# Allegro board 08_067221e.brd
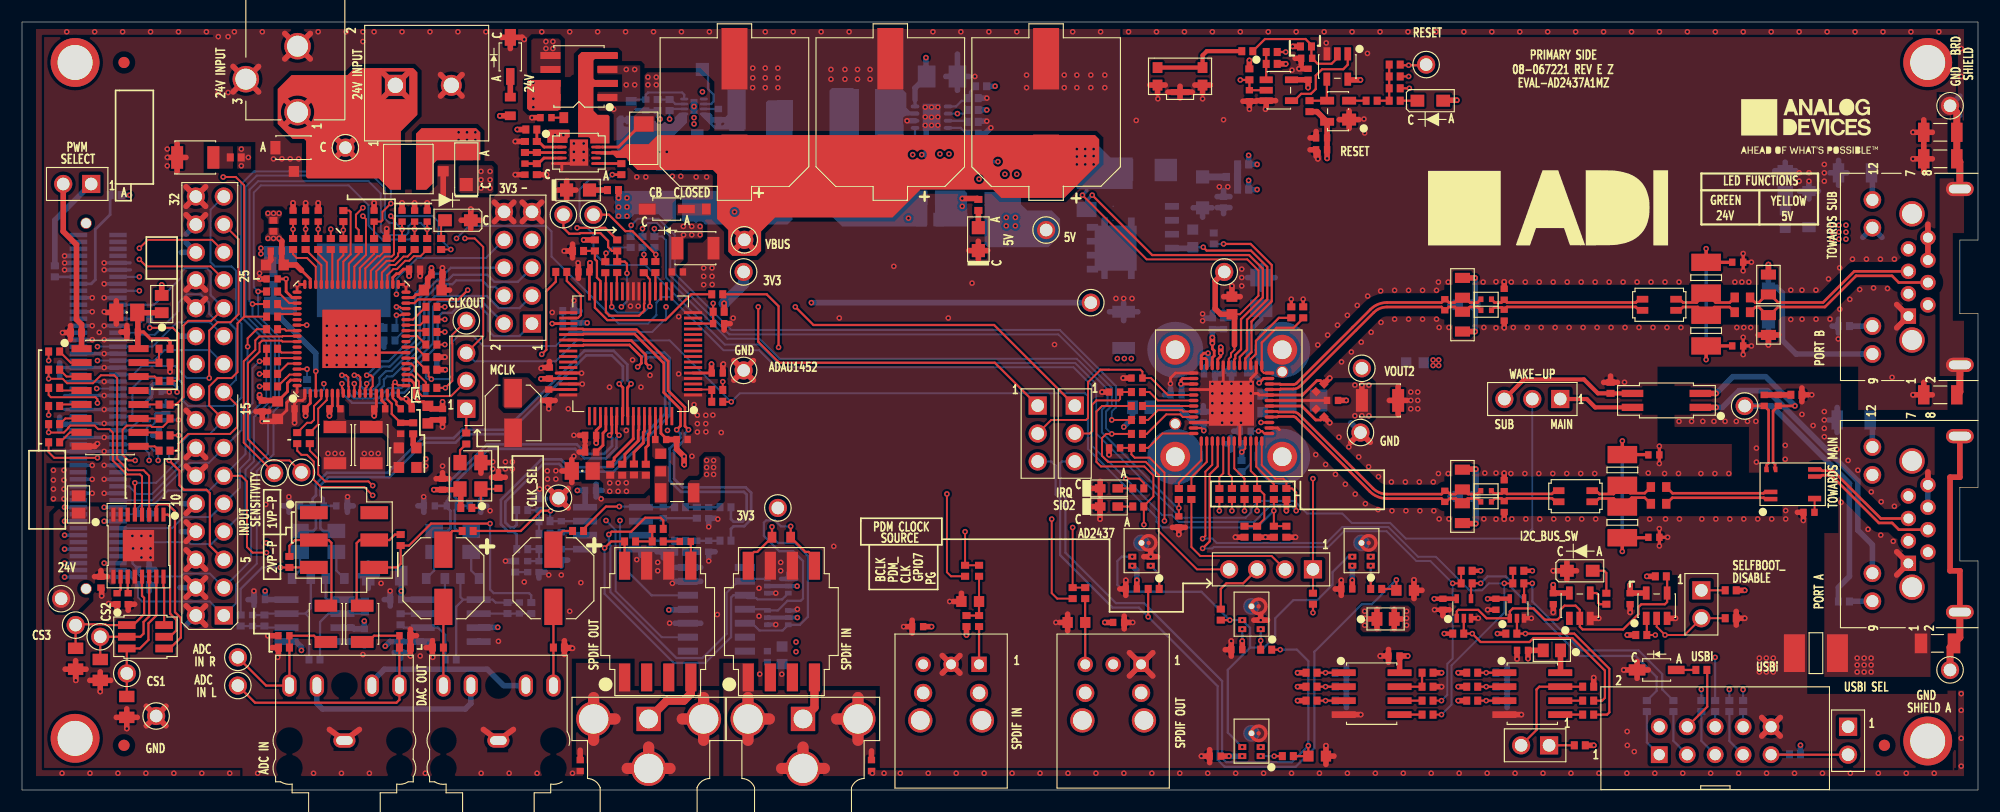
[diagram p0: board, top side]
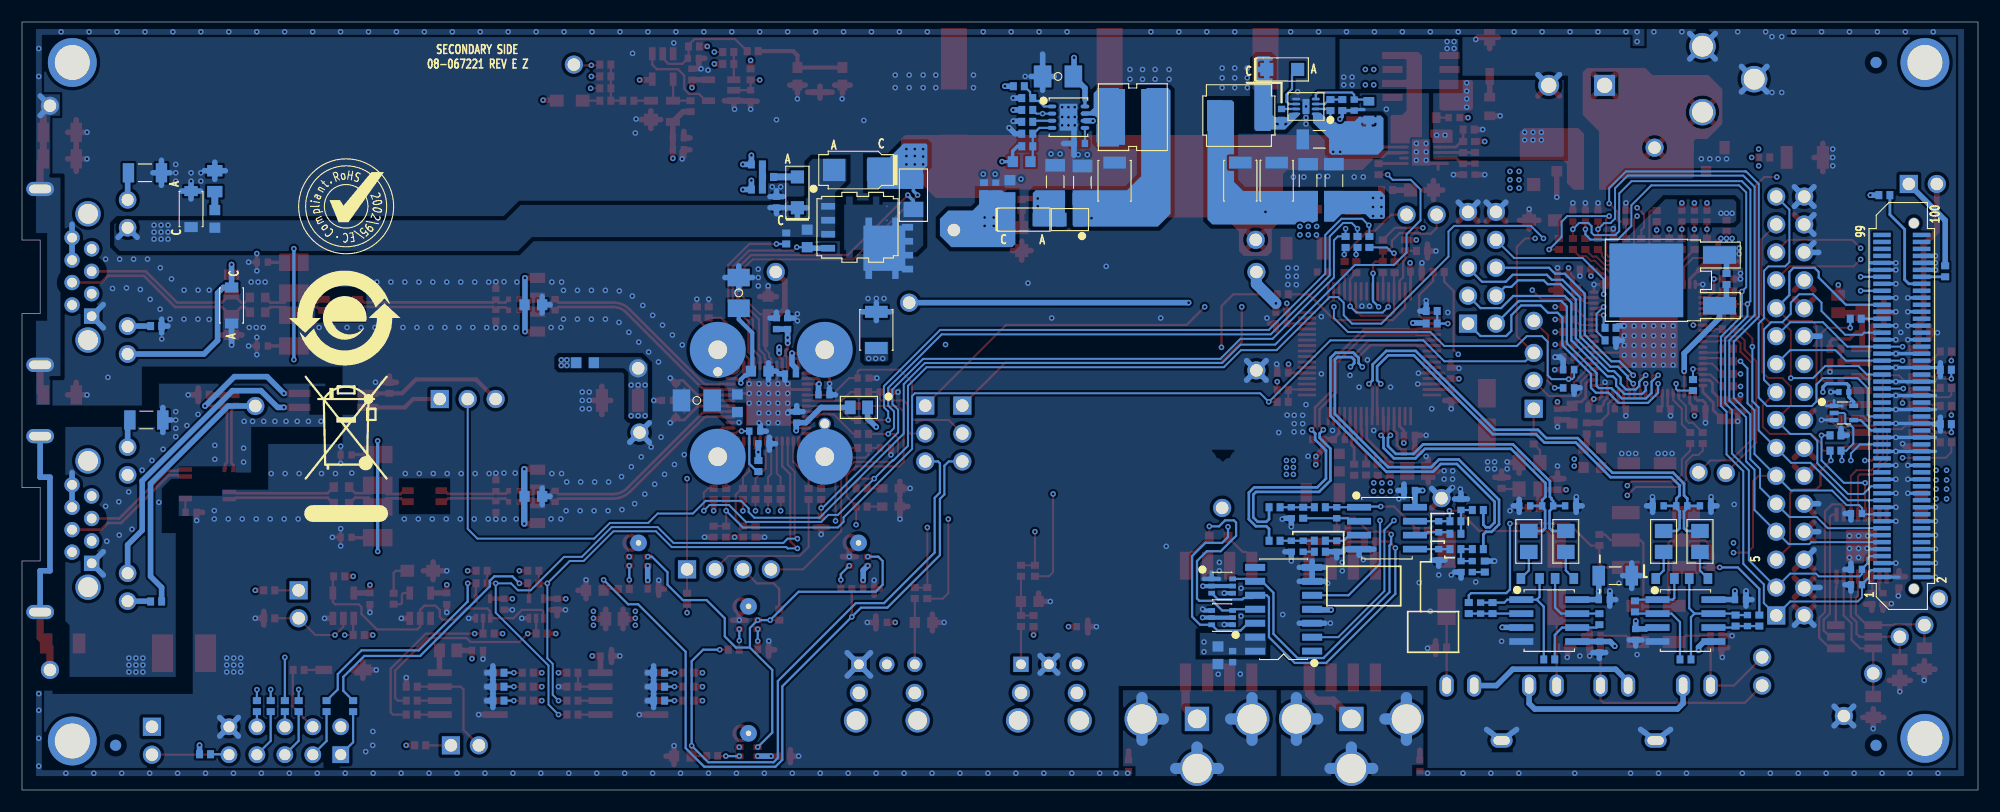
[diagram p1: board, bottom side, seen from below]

Outline 177.8 x 69.85 mm; copper layers: TOP, L2_GND, L3_SIG, L4_PWR, L5_GND, BOTTOM. Coordinates in mm from the lower left corner of the outline.
Outline path: 0,69.85 0,0 177.8,0 177.8,20.84 176.15,20.84 176.15,27.54 177.8,27.54 177.8,43.31 176.15,43.31 176.15,50.01 177.8,50.01 177.8,69.85 0,69.85

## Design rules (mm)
constraint set DEFAULT: min track width 0.178
net group AD243X_A: nets AD243X_AN AD243X_AP
net group AD243X_B: nets AD243X_BN AD243X_BP
net group ADC1L: nets ADC1LN ADC1LP
net group ADC1R: nets ADC1RN ADC1RP
net group DAC1L: nets DAC1LN DAC1LP
net group DAC1R: nets DAC1RN DAC1RP
net group DP1: nets UNNAMED_4_CAP_I21_N2 UNNAMED_4_CAP_I25_N2
net group DP2: nets UNNAMED_4_CAP_I73_N1 UNNAMED_4_CAP_I74_N2
net group DP3: nets UNNAMED_5_CAP_I145_N2 UNNAMED_5_CAP_I146_N2
net group DP4: nets UNNAMED_4_CAP_I139_N1 UNNAMED_4_TRANOPTO4PV2_I78_C
net group DP5: nets UNNAMED_4_CAP_I21_N1 UNNAMED_4_CAP_I25_N1
net group DP6: nets UNNAMED_5_CAP_I100_N2 UNNAMED_5_CAP_I105_N1
net group DP7: nets UNNAMED_5_CAP_I146_N1 UNNAMED_5_FLTR4PV7_I16_N3
net group DP_A2B: nets UNNAMED_4_MODRJE7318800XXX_I171_4 UNNAMED_4_MODRJE7318800XXX_I171_5

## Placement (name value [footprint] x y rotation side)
C1  0.1uF  [C0402]  116.9 65.09 270 top
C2  0.1uF  [C0402]  111.57 63.14 90 top
C3  0.1uF  [C0402]  47.62 61.15 0 top
C4  0.1uF  [C0402]  136.4 12.7 180 top
C5  0.1uF  [C0402]  118.13 59.31 0 top
C6  4.7NF  [C0402]  45.72 56.47 90 top
C7  0.1uF  [C0603]  25.52 56.26 0 top
C8  0.1uF  [C0603]  38.29 57.07 90 top
C9  27pF  [C0402]  36.83 52.2 270 top
C10  27pF  [C0402]  35.69 52.2 270 top
C11  27pF  [C0402]  34.54 52.2 270 top
C12  27pF  [C0402]  32 52.2 270 top
C13  0.1uF  [C0603]  110.74 38.1 0 bottom
C14  4.7uF  [C1206H71]  112.65 45.21 270 bottom
C15  0.1uF  [C0402]  8.64 17.4 90 top
C16  27pF  [C0402]  26.92 52.2 270 top
C17  27pF  [C0402]  25.78 52.2 270 top
C18  27pF  [C0402]  24.64 52.2 270 top
C19  47uF  [CPLSMSQ260H240]  48.3 19.26 90 top
C20  10UF  [C1210-2]  63.75 55.42 270 bottom
C21  10UF  [C1210-2]  67.06 55.42 270 bottom
C22  0.1uF  [C0402]  110.36 31.5 0 bottom
C23  0.1uF  [C0402]  23.11 49.02 180 top
C24  0.033uF  [C0402]  155.96 48.01 180 top
C25  4.7NF  [C0402]  81.68 58.8 180 bottom
C26  0.1uF  [C0402]  35.69 47.37 180 top
C27  0.1uF  [C0402]  22.73 46.48 0 top
C28  10UF  [C1210-2]  78.49 55.41 270 bottom
C29  4.7uF  [C0603]  88.01 54.67 270 bottom
C30  12pF  [C0402]  129.33 26.71 270 top
C31  0.1uF  [C0603]  112.78 35.17 270 bottom
C32  4.7uF  [C1206H71]  116.46 35.43 180 bottom
C33  0.33uF  [C0603]  131.32 26.71 0 bottom
C34  27pF  [C0402]  134.73 25.78 90 top
C35  27pF  [C0402]  134.73 27.68 90 top
C36  0.1uF  [C0402]  37.72 46.86 180 top
C37  1uF  [C0805H60]  9.52 43.43 0 top
C38  0.1uF  [C0402]  10.03 41.66 0 top
C39  0.033uF  [C0402]  155.96 40.39 0 top
C40  0.1uF  [C0402]  107.38 33.91 270 bottom
C41  27pF  [C0402]  101.35 37.46 180 top
C42  0.1uF  [C0402]  38.23 34.16 90 top
C43  0.1uF  [C0402]  117.98 34.29 135 top
C44  4700pF  [C0402]  159.64 35.43 90 top
C45  12pF  [C0402]  129.33 44.13 270 top
C46  0.1uF  [C0603]  109.98 44.07 270 top
C47  10uF  [CAPSML169W169H217]  44.64 34.29 270 top
C48  0.33uF  [C0603]  131.32 44.13 0 bottom
C49  27pF  [C0402]  134.73 43.19 90 top
C50  27pF  [C0402]  134.73 45.09 90 top
C51  27pF  [C0402]  99.31 36.2 180 top
C52  0.1uF  [C0402]  21.84 34.92 90 top
C53  0.01uF  [C0603#2]  156.38 43.46 0 top
C54  0.01uF  [C0603#2]  156.38 44.79 0 top
C55  0.1uF  [C0402]  117.98 36.58 225 top
C56  0.1uF  [C0402]  25.27 34.67 0 top
C57  10NF  [C0402]  119.13 35.43 180 top
C58  150pF  [C0402]  34.42 32.89 270 top
C59  10UF  [C1210-2]  123.44 35.43 180 top
C60  390pF  [C0402]  58.05 31.88 180 top
C61  0.1uF  [C0402]  32.51 34.67 0 top
C62  0.1uF  [C0402]  28.45 34.67 0 top
C63  5600pF  [C0603]  58.05 29.78 90 top
C64  27pF  [C0402]  99.31 31.12 180 top
C65  0.033uF  [C0402]  148.34 22.99 180 top
C66  0.1uF  [C0402]  51.07 47.12 0 top
C67  0.1uF  [C0402]  38.23 27.81 90 top
C68  0.01uF  [C0603#2]  148.76 26.03 0 top
C69  0.01uF  [C0603]  22.99 47.75 0 top
C70  0.01uF  [C0603#2]  148.76 27.55 0 top
C71  27pF  [C0402]  105.16 24.38 90 top
C72  0.033uF  [C0402]  162.43 25.26 180 top
C73  0.01uF  [C0603]  37.34 45.47 180 top
C74  10UF  [C1210-2]  15.75 57.53 0 top
C75  0.1uF  [C0402]  120.42 18.29 0 top
C76  0.01uF  [C0603]  23.24 34.54 90 top
C77  0.1uF  [C0402]  100.84 18.29 0 top
C78  0.01uF  [C0603]  36.89 34.14 90 top
C79  10UF  [C1210-2]  31.75 31.37 90 top
C80  0.033uF  [C0402]  148.34 30.48 0 top
C81  10UF  [C1210-2]  28.45 31.37 90 top
C82  22uF  [C1206]  32.97 19.49 0 bottom
C83  47uF  [C0805H60]  50.93 29.02 0 top
C84  33pF  [C0603]  125.73 18.16 180 top
C85  0.1uF  [C0402]  7.18 18.9 90 top
C86  5600pF  [C0603]  35.05 31.12 0 top
C87  0.1uF  [C0402]  9.65 17.4 90 top
C88  0.1uF  [C0402]  37.21 38.23 180 bottom
C89  0.1uF  [C0402]  110.42 12.76 0 top
C90  10UF  [C1210-2]  30.92 15.11 90 top
C91  10UF  [C1210-2]  27.62 15.11 90 top
C92  100pF  [C0402]  34.81 14.03 180 top
C93  100pF  [C0402]  23.81 14.03 0 top
C94  0.1uF  [C0402]  124.71 12.19 180 top
C95  0.1uF  [C0402]  59.58 47.12 180 top
C96  0.1uF  [C0402]  108.46 3.08 0 top
C97  0.1uF  [C0402]  109.22 42.42 270 bottom
C98  4700pF  [C0402]  158.37 35.43 90 top
C99  0.01uF  [C1206]  174.12 13.33 0 top
C100  33pF  [C0603]  117.73 3.08 180 top
C101  4.7uF  [C1206H71]  83.63 64.9 180 bottom
C102  0.01uF  [C1812H110]  163.07 12.45 0 top
C103  330uF  [CPLSMSQ512H650]  78.93 61.66 90 top
C104  330uF  [CPLSMSQ512H650]  93.09 61.66 90 top
C105  0.1uF  [C0402]  56.71 62.29 90 bottom
C106  270pF  [C0402]  62.42 25.22 90 bottom
C107  0.1uF  [C0402]  47.94 37.93 270 top
C108  0.1uF  [C0402]  60.01 31.88 180 top
C109  0.1uF  [C0402]  51.69 32.26 0 top
C110  0.1uF  [C0402]  63.2 37.93 180 top
C111  10UF  [C1210-2]  61.21 49.28 180 top
C112  0.1uF  [C0402]  51.69 30.73 0 top
C113  0.1uF  [C0402]  63.31 61.44 270 bottom
C114  1uF  [C1206]  59.88 59.18 180 bottom
C115  10pF  [C0603]  86.93 57.15 180 bottom
C116  0.033uF  [C0402]  109.22 53.47 90 bottom
C117  0.1uF  [C0603]  160.27 51.94 90 bottom
C118  22uF  [C1206]  60.9 55.42 270 bottom
C119  22uF  [C1206]  58.55 55.42 270 bottom
C120  22uF  [C1206]  83.88 55.31 270 bottom
C121  22uF  [C1206]  81.41 55.26 270 bottom
C122  0.033uF  [C0402]  89.28 54.74 270 bottom
C123  10UF  [C1210-2]  100.14 41.85 270 bottom
C124  10NF  [C0402]  108.2 42.42 270 bottom
C125  27pF  [C0402]  37.21 36.58 0 bottom
C126  10NF  [C0402]  107.95 37.85 180 bottom
C127  0.1uF  [C0402]  47.88 35.93 90 top
C128  0.1uF  [C0402]  104.9 35.94 0 bottom
C129  0.1uF  [C0402]  34.92 34.67 0 top
C130  47uF  [CPLSMSQ260H240]  38.3 19.26 90 top
C131  0.1uF  [C0402]  116.78 66.55 0 top
C132  330uF  [CPLSMSQ512H650]  64.76 61.66 90 top
C133  1000pF  [C0402]  41.2 25.84 180 bottom
C134  100pF  [C0402]  39.12 25.84 0 bottom
C135  1000pF  [C0402]  37.03 25.84 0 bottom
C136  1000pF  [C0402]  29.08 25.84 180 bottom
C137  0.1uF  [C0402]  31.12 14.15 90 bottom
C138  0.1uF  [C0402]  34.42 13.01 90 bottom
C139  100pF  [C0402]  26.92 25.84 180 bottom
C140  1000pF  [C0402]  24.77 25.84 0 bottom
C141  27pF  [C0402]  11.05 25.15 0 bottom
C142  10uF  [C0805H53]  40.83 22.61 90 bottom
C143  10uF  [C0805H53]  37.47 22.61 90 bottom
C144  10uF  [C0805H53]  28.57 22.61 90 bottom
C145  0.1uF  [C0402]  33.97 17.32 0 bottom
C146  0.1uF  [C0402]  21.59 17.32 0 bottom
C147  10uF  [C0805H53]  25.27 22.61 90 bottom
C148  560pF  [C0402]  62.42 22.17 270 bottom
C149  270pF  [C0402]  47 25.97 270 bottom
C150  560pF  [C0402]  46.99 20.32 270 bottom
C151  27pF  [C0402]  11.05 18.67 0 bottom
C152  27pF  [C0402]  11.05 20.07 0 bottom
C153  47PF  [C0402]  77.22 2.22 90 top
C154  0.1uF  [C0402]  51.68 27.24 180 bottom
C155  68PF  [C0402]  58.29 25.22 90 bottom
C156  4.7uF  [C0603]  69.09 12.26 90 bottom
C157  270pF  [C0402]  20.96 15.41 90 bottom
C158  270pF  [C0402]  45.21 16.55 90 bottom
C159  0.1uF  [C0402]  67.75 12.13 90 bottom
C160  0.1uF  [C0402]  60.29 22.61 180 top
C161  150PF  [C0402]  58.29 22.17 90 bottom
C162  0.1uF  [C0402]  63.33 42.42 180 top
C163  0.1uF  [C0402]  118.13 58.23 0 top
C164  68PF  [C0402]  49.02 23.95 90 bottom
C165  150PF  [C0402]  49.02 21.41 90 bottom
C166  10uF  [C0402]  61.34 22.17 90 bottom
C167  10uF  [C0402]  45.97 20.32 90 bottom
C168  47PF  [C0402]  50.74 2.22 90 top
C169  0.1uF  [C0402]  146.18 17.4 270 top
C170  0.1uF  [C0402]  133.98 16.89 270 top
C171  0.1uF  [C0402]  129.16 16.89 270 top
C172  0.1uF  [C0402]  139.19 17.4 90 top
C173  0.1uF  [C0402]  111.19 32.64 0 bottom
C174  0.01uF  [C0603]  106.43 50.16 270 bottom
C175  0.1uF  [C0402]  12.19 36.2 180 bottom
C176  0.1uF  [C0402]  81.41 14.86 0 top
C177  33pF  [C0603]  86.19 17.14 0 top
C178  33pF  [C0603]  95.85 15.24 0 top
C179  0.1uF  [C0402]  99.69 15.24 180 top
D1  PMEG6010CEH,115  [SOD123F]  63.25 65.53 180 bottom
D2  PMEG6010CEH,115  [SOD123F]  86.74 51.88 180 bottom
D3  TPSMF4L30A  [SOD123FL]  24.68 58.42 180 top
D4  TPSMF4L30A  [SOD123FL]  162.43 52.83 90 bottom
D5  NRVTSA3100ET3G  [SMA]  101.98 56.39 0 bottom
D6  PMEG6010CEH,115  [SOD123F]  107.31 54.36 90 bottom
D7  PMEG6010CEH,115  [SOD123F]  40.39 56.47 90 top
D8  BAT54XY,115  [SOT363H43]  68.71 15.68 90 bottom
D9  BAT54XY,115  [SOT363H43]  68.71 18.55 270 bottom
D10  TPSMF4L30A  [SOD123FL]  158.75 44.07 270 bottom
DS1  HSMS-C170  [LED0805]  128.02 62.69 0 top
DS2  CMD28-21VGC/TR8  [LEDCMD28-21B]  44.39 66.67 270 top
DS3  CMD28-21VGC/TR8  [LEDCMD28-21B]  58.61 52.83 0 top
DS4  HSMA-C170-T0000  [LED0805]  39.62 51.82 180 top
DS5  CMD28-21VGC/TR8  [LEDCMD28-21B]  148.59 10.92 0 top
DS6  CLX6F-FKC-CNP1ST1E1BB7D3D3  [LEDSMSQ134H114]  11.22 13.94 270 top
DS7  SML-LXT0805GW-TR  [LXT0805]  86.93 50.1 90 top
DS8  SML-LXT0805GW-TR  [LXT0805]  50.55 54.57 0 top
DS9  APT1608LVBC/D  [LED0603]  98.81 27.43 0 top
DS10  APT1608LVBC/D  [LED0603]  98.81 25.78 0 top
DS11  HSMS-C170  [LED0805]  141.6 19.94 0 top
E1  600OHM AT 100MEGHZ  [L0603-2]  101.73 34.8 0 bottom
E2  600 OHM AT 100 MEGHZ  [L0603]  126.62 38.86 180 bottom
E3  600OHM AT 100MEGHZ  [L0603-2]  82.55 51.88 0 bottom
E6  600OHM AT 100MEGHZ  [L0603]  35.05 29.34 180 top
E9  600OHM AT 100MEGHZ  [L0603-2]  12.7 44.2 90 top
E11  600OHM AT 100MEGHZ  [L0603-2]  5.14 25.97 90 top
E12  600OHM AT 100MEGHZ  [L0603-2]  123.95 15.56 0 top
E16  600OHM AT 100MEGHZ  [L0603-2]  139.06 12.7 180 top
E18  470OHM AT 100MEGHZ  [L0603]  59.75 52.26 180 bottom
FL1  ACT1210L-101-2P-TL00  [FLSML154W98H98]  148.83 44.13 0 top
FL2  ACT1210L-101-2P-TL00  [FLSML154W98H98]  141.21 26.72 0 top
JP1  TSW-104-07-G-S  [CNTHMHDR1X4L400W98H343]  117.35 20.07 180 top
JP2  TSW-102-07-G-S  [CNTHMHDR1X2L200W98H343]  152.65 18.16 270 top
JP3  TSW-102-07-G-S  [CNTHMHDR1X2L200W98H343]  138.81 4.06 180 top
JP4  TSW-103-07-G-S  [CNTHMHDR1X3L300W98H343]  139.83 35.56 180 top
JP6  TSW-103-07-G-S  [CNTHMHDR1X3L300W98H343]  92.32 34.96 270 top
JP9  TSW-103-07-G-S  [CNTHMHDR1X3L300W98H343]  95.69 34.96 270 top
JP38  TSW-103-07-G-S  [CNTHMHDR1X3L300W98H343]  40.39 34.67 90 top
JP42  HTSW-102-07-T-S  [CNTHMHDR1X2L200W98H343]  165.99 5.75 270 top
JP47  TSW-102-07-G-S  [CNTHMHDR1X2L200W98H343]  6.29 55.12 180 top
L1  3.3UH  [L0805H57]  158.75 45.97 90 top
L2  3.3UH  [L0805H57]  130.93 25.18 90 top
L3  3.3UH  [L0805H57]  130.93 28.23 90 top
L4  180NH  [L0402-3]  133.08 26.21 0 top
L5  180NH  [L0402-3]  133.08 27.21 0 top
L6  3.3UH  [L0805H57]  158.75 42.29 90 top
L7  4.7UH  [LSML213W201H59]  67.18 61.34 0 bottom
L8  3.3UH  [L0805H57]  130.94 42.6 90 top
L9  3.3UH  [L0805H57]  130.94 45.67 90 top
L10  180NH  [L0402-3]  133.09 43.63 0 top
L11  180NH  [L0402-3]  133.09 44.63 0 top
L12  100uH  [LSMSQ189H118_A]  76.83 61.19 180 bottom
L13  4.7uH  [LSMSQ157H122]  35.12 56.48 0 top
NOREF  -  []  0 0 90 top
NOREF#2  -  []  177.8 27.54 0 top
NOREF#3  -  []  177.8 0 0 top
NOREF#4  -  []  162.18 60.32 0 top
NOREF#5  -  []  176.15 20.84 0 top
NOREF#6  -  [unnamed#2]  4.83 4.7 0 top
NOREF#7  -  []  82.3 159.61 0 top
NOREF#8  -  []  0 69.85 0 top
NOREF#9  -  []  230.93 275.67 0 top
NOREF#10  -  []  0 69.85 0 top
NOREF#11  -  []  -22.8 311.15 0 top
NOREF#12  -  []  -39.78 -55.14 0 top
NOREF#13  -  []  42.06 169.52 0 top
NOREF#14  -  []  80.58 133.99 0 top
NOREF#15  -  []  -39.78 -55.14 0 top
NOREF#16  -  []  0 69.85 0 top
NOREF#17  -  []  28.65 159.61 90 top
NOREF#18  -  []  42.06 159.61 0 top
NOREF#19  -  [unnamed#2]  9.27 4.06 0 top
NOREF#20  -  []  79.63 80.67 0 top
NOREF#21  -  []  160.8 33.66 0 top
NOREF#22  -  []  0 0 0 top
NOREF#23  -  []  177.8 50.01 0 top
NOREF#24  -  []  177.8 69.85 180 top
NOREF#25  -  []  176.35 47.65 0 top
NOREF#26  -  []  216.22 239.52 0 top
NOREF#27  -  []  4.83 4.7 0 top
NOREF#28  -  []  177.8 0 90 top
NOREF#29  -  []  157.86 11.43 0 top
NOREF#30  -  []  177.8 0 90 top
NOREF#31  -  []  -39.78 -55.14 0 top
NOREF#32  -  []  177.8 20.84 0 top
NOREF#33  -  []  194.8 11.19 0 top
NOREF#34  -  []  -39.78 -55.14 0 top
NOREF#35  -  []  28.49 -59.81 270 top
NOREF#36  -  []  4.83 4.7 0 top
NOREF#37  -  []  111.76 4.45 0 top
NOREF#38  -  []  127.81 49.53 0 top
NOREF#39  -  []  177.8 43.31 0 top
NOREF#40  -  [unnamed#2]  9.27 66.17 0 top
NOREF#41  -  []  0 0 0 top
NOREF#42  -  []  0 69.85 270 top
NOREF#43  -  [unnamed#2]  173.23 66.17 0 top
NOREF#44  -  [unnamed#2]  4.83 66.17 0 top
NOREF#45  -  [unnamed#2]  173.23 4.46 0 top
NOREF#46  -  [unnamed#2]  169.29 4.06 0 top
NOREF#47  -  []  0 0 0 top
NOREF#48  -  []  62.28 169.52 0 top
NOREF#49  -  []  116.1 28.77 0 top
NOREF#50  -  []  62.18 159.61 0 top
NOREF#51  -  [unnamed#2]  169.29 4.06 180 bottom
NOREF#52  -  []  148.46 42.93 180 bottom
NOREF#53  -  [unnamed#2]  9.27 4.06 180 bottom
NOREF#54  -  []  148.34 53.09 180 bottom
NOREF#55  -  [unnamed#2]  9.27 66.17 180 bottom
NOREF#56  -  []  139.06 41.27 180 bottom
P1  PJ-102AH  [CNCUI-PJ-102A_SLOTPAD]  25.05 61.65 90 top
P2  1716020000  [CNWEIDMULLER171602]  33.94 64.09 0 top
P3  RCJ-011  [CNCUIRCJ-01]  70.99 6.46 180 top
P4  FCR684208R  [CNCLIFF_FCR684208R]  86.99 11.43 180 top
P5  RCJ-011  [CNCUIRCJ-01]  56.96 6.46 180 top
P6  FCR684208T  [CNCLIFF_FCR684208T]  101.73 11.43 180 top
P8  TSW-105-07-G-D  [CNSAMTEC2X5H338LD36]  46.36 42.42 90 top
P10  RJE73-188-00210  [MRJE73-188-00XXX]  171.47 43.09 90 top
P15  TSW-116-08-G-D  [CNBERG2X16H330LD36]  18.34 15.88 90 top
P22  RJE73-188-00210  [MRJE73-188-00XXX]  171.47 20.62 90 top
P23  TESTPAD  [TPC65D45]  127.63 65.98 90 top
P28  SJ1-3525NG  [CNCUISJ1-3525NG]  43.3 4.5 90 top
P29  SJ1-3525NG  [CNCUISJ1-3525NG]  29.31 4.5 90 top
P30  N2510-6002-RB  [CN3MN2510-6002RB]  148.83 3.21 0 top
P32  LSS-150-01-L-DV-A-K  [CNSAMTECLSS-150-01-X-DV-A]  6.93 34.92 90 bottom
Q1  DMNH6022SSDQ-13  [SO8NB-5]  50.63 64.9 90 top
Q2  TLX9291A(GBTPL,F  [SO4H96]  149.48 35.43 90 top
Q3  STD2805T4  [TO252]  27.56 46.35 90 bottom
Q4  DMTH8012LPSQ-13  [POWERDI5060-8]  101.85 51.18 270 bottom
R1  100  [R0402]  113.6 67.12 180 top
R2  10K  [R0402]  113.6 66.04 180 top
R3  0  [R0402]  124.78 65.98 180 top
R4  1K  [R0402]  124.78 62.69 0 top
R5  10K  [R0402]  111.57 65.09 270 top
R6  0  [R0402]  124.78 64.9 180 top
R7  10K  [R0402]  110.86 29.46 90 bottom
R8  0  [R0402]  122.68 62.69 180 top
R9  10K  [R0402]  117.03 62.19 90 top
R10  4.7K  [R0603]  44.39 62.17 270 top
R11  33  [R0402]  109.98 26.92 90 top
R12  10K  [R0402]  113.79 23.49 270 top
R13  22K  [R0603]  50.1 61.15 0 top
R14  33  [R0402]  106.3 26.92 90 top
R15  10K  [R0402]  131.83 10.67 180 top
R16  10K  [R0402]  134.49 10.67 180 bottom
R17  4.42MEG  [R0402]  46.3 60.07 180 top
R18  0.012  [R1206-2]  56.52 59.27 270 top
R19  10K  [R0402]  131.83 9.4 180 top
R20  88.7K  [R0402]  46.8 58.48 90 top
R21  10K  [R0402]  114.93 23.49 90 top
R22  10K  [R0402]  112.27 23.49 270 top
R23  11.3K  [R0402]  45.72 58.48 270 top
R24  10K  [R0402]  134.49 9.4 180 bottom
R25  33  [R0402]  142.37 8.13 0 top
R26  10K  [R0402]  131.83 8.13 180 top
R27  1MEG  [R0402]  54.48 56.47 270 top
R28  0  [R0402]  46.8 56.47 270 top
R29  33  [R0402]  142.37 6.86 0 top
R30  10K  [R0402]  134.49 8.13 180 bottom
R31  0  [R1206]  174.37 59.82 0 top
R32  4.7K  [R0603]  63.06 52.83 0 top
R33  1K  [R0402]  53.72 54.57 0 top
R34  475  [R0402]  101.47 25.78 0 top
R35  33  [R0402]  127.76 8.13 0 top
R36  1K  [R0402]  86.93 53.21 90 top
R37  0  [R0402]  22.86 51.31 90 top
R38  475  [R0402]  101.47 27.43 0 top
R39  2.55K  [R0402]  135.38 14.22 180 top
R40  100  [R1210]  145.47 24.34 90 top
R41  100  [R1210]  145.47 29.11 270 top
R42  10K  [R0402]  144.4 36.58 270 top
R43  0  [R0402]  54.56 29.13 270 top
R44  33  [R0402]  36.83 49.66 90 top
R45  33  [R0402]  35.69 49.66 90 top
R46  205  [R0402]  165.61 17.14 180 bottom
R47  33  [R0402]  34.54 49.66 90 top
R48  33  [R0402]  32 49.66 90 top
R49  33  [R0402]  29.21 52.2 270 top
R50  33  [R0402]  26.92 49.66 90 top
R51  33  [R0402]  25.78 49.66 90 top
R52  33  [R0402]  24.64 49.66 90 top
R53  2.55K  [R0402]  130.56 14.22 180 top
R54  0  [R0402]  101.35 36.2 0 top
R55  0  [R0402]  136.02 18.8 180 top
R56  120  [R1210]  153.09 46.59 270 top
R57  0  [R0402]  54.1 49.53 90 top
R58  33  [R0402]  56.52 47.55 270 top
R59  33  [R0402]  53.02 47.55 270 top
R60  0  [R0402]  53.47 29.13 270 top
R61  0  [R0402]  56.71 29.13 270 top
R62  0  [R0402]  22.73 45.34 180 top
R63  0  [R0402]  22.73 44.2 180 top
R64  33  [R0402]  37.21 43.94 180 top
R65  100  [R0402]  161.29 35.94 180 top
R66  33  [R0402]  22.73 43.05 0 top
R67  33  [R0402]  22.73 41.91 0 top
R68  33  [R0402]  22.73 38.99 0 top
R69  33  [R0402]  30.61 49.66 270 top
R70  0  [R0402]  131.32 18.8 180 top
R71  33  [R0402]  22.73 36.7 0 top
R72  100K  [R0402]  116.46 43.44 270 top
R73  100K  [R0402]  115.38 43.44 270 top
R74  10K  [R0402]  141.6 4.06 0 top
R75  3.32K  [R0402]  38.1 49.66 90 top
R76  33  [R0402]  37.21 42.8 0 top
R77  0  [R0402]  37.21 41.66 0 top
R78  120  [R1210]  153.09 41.78 90 top
R79  0  [R0402]  37.21 40.51 0 top
R80  10K  [R0402]  4.91 41.6 180 top
R81  33  [R0402]  22.73 40.13 0 top
R82  10K  [R0402]  12.95 38.86 0 top
R83  10K  [R0402]  12.95 40.13 0 top
R84  33  [R0402]  28.07 49.66 90 top
R85  0  [R0402]  37.21 39.37 0 top
R86  0  [R0402]  2.92 39.88 0 top
R87  0  [R0402]  22.73 37.85 0 top
R88  33  [R0402]  37.21 36.58 0 top
R89  0  [R0402]  12.95 37.21 180 top
R90  33  [R0402]  2.92 38.23 180 top
R91  0  [R0402]  63.2 35.31 0 top
R92  0  [R0402]  2.92 36.58 0 top
R93  100K  [R0402]  155.32 15.62 180 top
R94  0  [R0402]  63.2 36.39 0 top
R95  10K  [R0402]  147.19 14.1 180 top
R96  0  [R1206]  174.37 35.94 0 top
R97  0  [R0402]  2.92 34.92 0 top
R98  33  [R0402]  101.35 34.92 0 top
R99  4.32K  [R0402]  35.56 32.89 270 top
R100  0  [R0402]  12.95 35.05 180 top
R101  10K  [R0402]  116.71 67.63 0 top
R102  33  [R0402]  2.92 33.27 180 top
R103  33  [R0402]  86.99 15.37 90 top
R104  33  [R0402]  57.57 47.56 270 top
R105  33  [R0402]  54.1 47.56 90 top
R106  0  [R0402]  12.95 33.78 180 top
R107  10K  [R0402]  37.21 38.23 180 top
R108  33  [R0402]  12.95 32.26 0 top
R109  33  [R0402]  40.39 31.97 90 top
R110  10K  [R0402]  43.31 27.94 270 top
R111  0  [R0402]  2.92 31.62 0 top
R112  0  [R1206]  174.37 57.4 0 top
R113  0  [R0402]  12.95 30.86 180 top
R114  33  [R0402]  101.35 31.12 0 top
R115  10K  [R0402]  40.39 25.65 180 top
R116  33  [R0402]  26.16 32 270 top
R117  562  [R1206]  59.55 27.03 180 top
R118  10K  [R0402]  114.93 26.92 90 top
R119  10K  [R0402]  85.85 15.37 90 top
R120  33  [R0402]  108.84 26.92 90 top
R121  33  [R0402]  105.16 26.92 90 top
R122  2.55K  [R0402]  131.32 19.94 0 top
R123  5.36K  [R0402]  34.42 22.73 270 top
R124  0  [R0402]  55.63 29.15 270 top
R125  0  [R0402]  117.35 17.4 90 top
R126  2.55K  [R0402]  136.02 19.94 0 top
R127  0  [R0402]  86.99 19.94 90 top
R128  100K  [R0402]  48.8 12.95 180 top
R129  5.36K  [R0402]  24.31 20.74 270 top
R130  33  [R0402]  123.1 18.29 0 top
R131  33  [R0402]  102.87 18.29 180 top
R132  33  [R0402]  49.02 47.12 180 top
R133  10K  [R0402]  119.89 8.13 180 bottom
R134  0  [R0402]  124.78 63.82 180 top
R135  10K  [R0402]  111.12 23.49 90 top
R136  100  [R0402]  111.38 67.19 0 top
R137  10K  [R0402]  117.22 8.13 180 top
R138  33  [R0402]  63.2 45.09 0 top
R139  10K  [R0402]  117.22 9.4 180 top
R140  33  [R0402]  29.21 49.66 90 top
R141  33  [R0402]  113.1 12.76 0 top
R142  10K  [R0402]  52.07 49.53 90 top
R143  10K  [R0402]  50.55 49.02 0 top
R144  100K  [R0402]  34.81 12.95 180 top
R145  100K  [R0402]  23.81 12.95 0 top
R146  10K  [R0402]  119.89 9.4 180 bottom
R147  10K  [R0402]  119.89 10.67 180 bottom
R148  10K  [R0402]  117.22 10.67 180 top
R149  100K  [R0402]  2.92 33.27 180 bottom
R150  100K  [R0402]  2.92 38.23 180 bottom
R151  10  [R0805]  4.87 11.94 90 top
R152  10  [R0805]  7.11 10.92 90 top
R153  10  [R0805]  9.52 7.56 90 top
R154  10K  [R0402]  87.19 64.01 180 bottom
R155  1K  [R0402]  152.65 10.92 0 top
R156  100K  [R0402]  12.95 32.26 0 bottom
R157  0  [R0402]  108.97 15.95 90 top
R158  33  [R0402]  115.06 3.08 0 top
R159  100K  [R0402]  86.42 62.93 180 bottom
R160  31.6K  [R0402]  58.86 62.29 90 bottom
R161  100K  [R0402]  86.42 61.85 0 bottom
R162  24.9K  [R0603]  55.37 61.79 270 bottom
R163  0  [R0402]  86.42 60.77 180 bottom
R164  10.2K  [R0402]  86.42 59.69 180 bottom
R165  0  [R0402]  111 54.61 0 bottom
R166  0  [R0402]  111 56.9 0 bottom
R167  53.6K  [R0402]  86.42 58.55 0 bottom
R168  12  [R0805]  160.27 55.37 90 bottom
R169  0  [R0402]  8.51 54.1 0 bottom
R170  100K  [R0402]  90.36 54.74 270 bottom
R171  0  [R0402]  57.48 49.85 90 bottom
R172  0  [R0402]  56.4 49.85 90 bottom
R173  0  [R0402]  55.33 49.85 90 bottom
R174  0  [R0402]  2.98 47.17 90 bottom
R175  1K  [R0402]  22.86 46.48 90 bottom
R176  1K  [R0402]  33.15 49.66 90 top
R177  0  [R0402]  11.11 42.86 180 bottom
R178  10K  [R0402]  33.4 40.89 0 bottom
R179  10K  [R0402]  33.4 42.04 0 bottom
R180  10K  [R0402]  155.32 18.16 0 top
R181  0  [R0402]  108.33 50.16 90 bottom
R182  0.05  [R1206-2]  96.77 54.1 90 bottom
R183  33  [R0402]  25.91 36.83 90 bottom
R184  10K  [R0402]  57.79 62.29 90 bottom
R185  10K  [R0402]  49.66 42.43 0 bottom
R186  0.5  [R0402]  19.43 57.53 0 top
R187  10K  [R0402]  63.33 43.5 180 top
R188  75  [R0603]  69.02 22.99 180 top
R189  0  [R0402]  12.95 30.86 0 bottom
R190  10K  [R0402]  49.66 43.56 180 bottom
R192  5.62K  [R0402]  63.94 22.67 180 bottom
R193  33  [R0402]  25.02 32 90 top
R194  11K  [R0402]  63.94 25.72 180 bottom
R195  33  [R0402]  112.27 26.92 90 top
R196  237  [R0603]  40.7 19.24 0 bottom
R197  237  [R0603]  37.59 19.24 180 bottom
R198  237  [R0603]  28.45 19.24 0 bottom
R199  33  [R0402]  111.12 26.92 90 top
R200  237  [R0603]  25.4 19.24 180 bottom
R201  5.36K  [R0402]  31.18 16.7 90 bottom
R202  5.36K  [R0402]  34.42 15.54 90 bottom
R203  33  [R0402]  127.76 6.86 0 top
R204  5.36K  [R0402]  22.03 15.41 90 bottom
R205  5.36K  [R0402]  19.88 15.41 270 bottom
R206  249  [R0402]  57.79 23.75 180 top
R207  5.36K  [R0402]  46.29 16.55 270 bottom
R208  5.36K  [R0402]  44.13 16.55 90 bottom
R209  110  [R0402]  55.28 22.61 0 top
R210  0  [R0402]  57.79 22.61 180 top
R211  5.62K  [R0402]  45.47 21.91 0 bottom
R212  11K  [R0402]  45.47 25.46 0 bottom
R213  5.36K  [R0402]  38.97 11.87 0 bottom
R214  5.36K  [R0402]  26.59 11.87 180 bottom
R215  5.62K  [R0402]  59.82 21.67 0 bottom
R216  5.62K  [R0402]  44.83 20.32 270 bottom
R217  11K  [R0402]  59.82 25.72 180 bottom
R218  11K  [R0402]  47.5 24.45 0 bottom
R219  3.01K  [R0402]  61.34 25.22 270 bottom
R220  100  [R0402]  109.98 55.75 0 bottom
R221  1.5K  [R0402]  59.82 22.67 180 bottom
R222  3.01K  [R0402]  47.5 23.3 0 bottom
R223  0  [R0402]  156.45 7.63 270 bottom
R224  1.5K  [R0402]  47.5 21.91 0 bottom
R225  0  [R0402]  153.91 7.63 270 bottom
R226  0  [R0402]  85.72 19.94 90 top
R227  0  [R0402]  96.65 17.91 90 top
R228  0  [R0402]  95.5 17.91 90 top
R231  10K  [R0402]  161.16 3.25 180 bottom
R232  33  [R0402]  152.65 7.63 270 bottom
R233  0  [R0402]  150.11 7.63 270 bottom
R234  0  [R0402]  147.7 7.63 270 bottom
R235  33  [R0402]  155.19 7.63 270 bottom
R236  100  [R0402]  50.55 23.56 180 top
R237  100  [R0402]  40.51 23.56 180 top
R238  10K  [R0402]  148.97 19.43 180 top
R239  330  [R0402]  144.02 17.4 90 top
R240  33  [R0402]  101.35 33.66 0 top
R241  33  [R0402]  101.35 32.38 0 top
R242  33  [R0402]  113.79 26.92 90 top
R243  10K  [R0402]  127.76 10.67 0 top
R244  100K  [R0402]  127.76 9.4 180 top
R246  100K  [R0402]  142.37 9.4 180 top
R247  2.74K  [R1206]  166.5 33.66 180 bottom
R248  365  [R0402]  165.61 42.19 0 bottom
R249  2.74K  [R1206]  166.62 56.13 180 bottom
R250  100K  [R0402]  37.8 12.95 0 top
S1  JS202011SCQN  [SWSML354W142H217]  29.27 22.73 270 top
SW1  KMR223GLFG  [SWSML165W110H75-G]  105.27 64.91 0 top
T1  74930000  [TSML185W127H114_A]  160.96 27.81 0 top
T2  SC947-02LF  [TSML387W323H220]  69.02 15.32 0 top
T3  SC947-02LF  [TSML387W323H220]  57.79 15.32 0 top
TP1  TESTPAD  [TPC65D45]  29.4 58.42 0 top
TP2  TESTPAD  [TPC65D45]  175.26 62.23 0 top
TP3  TESTPAD  [TPC65D45]  93.09 50.93 0 top
TP4  TESTPAD  [TPC65D45]  175.26 10.92 0 top
TP5  TESTPAD  [TPC65D45]  19.62 12.06 0 top
TP6  TESTPAD  [TPC65D45]  19.62 9.5 0 top
TP7  TESTPAD  [TPC65D45]  51.94 52.32 0 top
TP8  TESTPAD  [TPC65D45]  49.21 52.32 0 top
TP9  TESTPAD  [TPC65D45]  48.77 26.54 0 top
TP10  TESTPAD  [TPC65D45]  68.71 25.65 0 top
TP11  TESTPAD  [TPC65D45]  97.15 44.32 0 top
TP12  TESTPAD  [TPC65D45]  65.6 38.16 0 top
TP13  TESTPAD  [TPC65D45]  109.28 47.12 0 top
TP14  TESTPAD  [TPC65D45]  121.67 32.51 0 top
TP15  TESTPAD  [TPC65D45]  121.79 38.35 0 top
TP16  TESTPAD  [TPC65D45]  25.4 28.89 0 top
TP17  TESTPAD  [TPC65D45]  22.92 28.83 0 top
TP18  TESTPAD  [TPC65D45]  40.39 42.67 0 top
TP19  TESTPAD  [TPC65D45]  3.56 17.4 0 top
TP20  TESTPAD  [TPC65D45]  9.52 10.6 0 top
TP21  TESTPAD  [TPC65D45]  12.19 6.73 0 top
TP22  TESTPAD  [TPC65D45]  7.11 13.94 0 top
TP23  TESTPAD  [TPC65D45]  4.87 15 0 top
TP24  TESTPAD  [TPC65D45]  65.6 47.12 0 top
TP25  TESTPAD  [TPC65D45]  65.66 50.04 0 top
TP26  TESTPAD  [TPC65D45]  156.59 34.92 0 top
U1  SN74LVC1G08QDBVRQ1  [SOT23-5L-2]  114.25 63.64 270 top
U2  ADM6315-31D1ARTZ  [SOT143A]  119.63 61.73 90 top
U3  LTC4368IDD-2#PBF  [DFN10_3X3_PAD2_38X1_65_05-08-1699]  50.63 57.98 270 top
U4  SN74CBTLV1G125DCKR  [SC70-5]  12.19 34.29 270 bottom
U5  ADA4841-2YRZ  [SO8]  53.72 23.81 270 bottom
U6  ADAU1452WBCPZ  [QFN72_10X10_PAD5_3X5_3]  29.96 41.03 0 top
U7  AD1937WBSTZ  [LQFP64]  55.33 39.68 90 top
U8  ADG774BRZ  [SO16NB-2]  8 35.7 270 top
U9  AD2437  [QFN48_7X7_PAD4_1X4_1]  109.69 35.17 270 top
U10  MAX16823AUE+  [TSSOP16_5X4_4_PAD2_85X2_85]  10.58 22.23 180 top
U11  MMICT3902-00-012  [LGA_CAV5_MEMS]  121.76 21.77 90 top
U12  MMICT3902-00-012  [LGA_CAV5_MEMS]  101.76 21.77 90 top
U13  MMICT3902-00-012  [LGA_CAV5_MEMS]  111.76 4.45 90 top
U14  MMICT3902-00-012  [LGA_CAV5_MEMS]  111.76 15.99 90 top
U15  24AA512T-I/SN  [SO8]  122.68 8.76 270 top
U16  LT3502AEDC#TRMPBF  [DFN8_2X2_PAD1_37X0_64]  61.09 62.17 90 bottom
U17  ADA4841-2YRZ  [SO8]  38.97 15.41 270 bottom
U18  ADA4841-2YRZ  [SO8]  26.59 15.41 270 bottom
U19  ADP2360ACPZ  [DFN8_3X3_PAD2_44X1_6]  82.68 61.19 270 bottom
U20  MAX22503EASD+  [SO14NB-2]  63.12 16.44 90 bottom
U21  24AA512T-I/SN  [SO8]  137.29 8.76 270 top
U24  SN74LVC1G08QDBVRQ1  [SOT23-5L-2]  119.56 65.8 180 top
U25  SN74LVC1G08QDBVRQ1  [SOT23-5L-2]  148.59 16.76 0 top
U26  SN74CBTLV1G125DCKR  [SC70-5]  135.89 16.51 0 top
U27  SN74CBTLV1G125DCKR  [SC70-5]  131.06 16.51 0 top
U28  SN74LVC1G04DBVR  [SOT23-5L-2]  141.6 16.76 0 top
Y1  24.576MEGHZ  [YSML126W98H47]  40.77 28.58 90 top

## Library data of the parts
C1-C5 C15 C22 C23 C26 C27 C36 C38 C40 C42 C43 C52 C55 C56 C61 C62 C66 C67 C75 C77 C85 C87-C89 C94-C97 C105 C107-C110 C112 C113 C127-C129 C131 C137 C138 C145 C146 C154 C159 C160 C162 C163 C172 C173 C175 C176 C179 = CAP: User Part Number: UPN; Tolerance: 10; alternate symbols: (C0402); part number: CAP_SM-0.1UF,35V,10,E019488,C0402; tolerance: 10
C6 C25 = CAP: User Part Number: UPN; Tolerance: 10; alternate symbols: (C0402); part number: CAP_SM-4.7NF,16V,10,E042800,C0402; tolerance: 10
C7 C8 C13 C31 C46 = CAP: User Part Number: UPN; Tolerance: 10; alternate symbols: (C0603); part number: CAP_SM-0.1UF,50V,10,E011865,C0603; tolerance: 10
C9-C12 C16-C18 C34 C35 C41 C49-C51 C64 C71 C125 C141 C151 C152 = CAP: User Part Number: UPN; Tolerance: 5; alternate symbols: (C0402); part number: CAP_SM-27PF,50V,5,E033384,C0402; tolerance: 5
C14 C32 C101 = CAP: Tolerance: 10; User Part Number: UPN; alternate symbols: (C1206H71); part number: CAP_SM-4.7UF,50V,10,E026699,C1206H71; tolerance: 10
C19 C130 = CAPP: Tolerance: 20; User Part Number: UPN; alternate symbols: (CPLSMSQ260H240); part number: CAPP_SM-47UF,10V,20,E018273,CPLSMSQ260H240; tolerance: 20
C20 C21 C28 C59 C74 C79 C81 C90 C91 C111 C123 = CAP: Tolerance: 10; User Part Number: UPN; alternate symbols: (C1210H106); part number: CAP_SM-10UF,25V,10,E013830,C1210-2; tolerance: 10
C24 C39 C65 C72 C80 C116 C122 = CAP: User Part Number: UPN; Tolerance: 10; alternate symbols: (C0402); part number: CAP_SM-0.033UF,50V,10,E019776,C0402; tolerance: 10
C29 C156 = CAP: User Part Number: UPN; Tolerance: 10; alternate symbols: (C0603); part number: CAP_SM-4.7UF,35V,10,E039350,C0603; tolerance: 10
C30 C45 = CAP: User Part Number: UPN; Tolerance: 5; alternate symbols: (C0402); part number: CAP_SM-12PF,50V,5,E034633,C0402; tolerance: 5
C33 C48 = CAP: User Part Number: UPN; Tolerance: 20; alternate symbols: (C0603); part number: CAP_SM-0.33UF,16V,20,E033782,C0603; tolerance: 20
C37 = CAP: Tolerance: 10; User Part Number: UPN; alternate symbols: (C0805H60); part number: CAP_SM-1UF,25V,10,E007664,C0805H60; tolerance: 10
C44 C98 = CAP: User Part Number: UPN; Tolerance: 5; alternate symbols: (C0402); part number: CAP_SM-4700PF,50V,5,E006445,C0402; tolerance: 5
C47 = CAPP: Tolerance: 20; User Part Number: UPN; alternate symbols: (CAPSML169W169H217); part number: CAPP_SM-10UF,16V,20,E005931,CAPSML169W169H217; tolerance: 20
C53 C54 C68 C70 C174 = CAP: User Part Number: UPN; Tolerance: 5; alternate symbols: (C0603L); part number: CAP_SM-0.01UF,50V,5,E019502,C0603; tolerance: 5
C57 C124 C126 = CAP: User Part Number: UPN; Tolerance: 10; alternate symbols: (C0402); part number: CAP_SM-10NF,25V,10,E046235,C0402; tolerance: 10
C58 = CAP: User Part Number: UPN; Tolerance: 5; alternate symbols: (C0402); part number: CAP_SM-150PF,50V,5,E012646,C0402; tolerance: 5
C60 = CAP: User Part Number: UPN; Tolerance: 5; alternate symbols: (C0402); part number: CAP_SM-390PF,50V,5,E033837,C0402; tolerance: 5
C63 C86 = CAP: User Part Number: UPN; Tolerance: 5; alternate symbols: (C0603); part number: CAP_SM-5600PF,25V,5,E017293,C0603; tolerance: 5
C69 C73 C76 C78 = CAP: User Part Number: UPN; Tolerance: 5; alternate symbols: (C0603); part number: CAP_SM-0.01UF,50V,5,E019502,C0603; tolerance: 5
C82 C118-C121 = CAP: User Part Number: UPN; Tolerance: 10; alternate symbols: (C1206); part number: CAP_SM-22UF,16V,10,E026209,C1206; tolerance: 10
C83 = CAP: Tolerance: 20; User Part Number: UPN; alternate symbols: (C0805H60); part number: CAP_SM-47UF,6.3V,20,E008247,C0805H60; tolerance: 20
C84 C100 C177 C178 = CAP: User Part Number: UPN; Tolerance: 5; alternate symbols: (C0603); part number: CAP_SM-33PF,50V,5,E000396,C0603; tolerance: 5
C92 C93 C134 C139 = CAP: User Part Number: UPN; Tolerance: 5; alternate symbols: (C0402); part number: CAP_SM-100PF,50V,5,E024302,C0402; tolerance: 5
C99 = CAP: User Part Number: UPN; Tolerance: 5; alternate symbols: (C1206); part number: CAP_SM-0.01UF,50V,5,E014026,C1206; tolerance: 5
C102 = CAP: Tolerance: 10; User Part Number: UPN; alternate symbols: (C1812H110); part number: CAP_SM-0.01UF,2000V,10,E023562,C1812H110; tolerance: 10
C103 C104 C132 = CAPP: User Part Number: UPN; Tolerance: 20; alternate symbols: (CPLSMSQ512H650); part number: CAPP_SM-330UF,63V,20,E040098,CPLSMSQ512H650; tolerance: 20
C106 C149 = CAP: User Part Number: UPN; Tolerance: 1; alternate symbols: (C0402); part number: CAP_SM-270PF,50V,1,E038922,C0402; tolerance: 1
C114 = CAP: User Part Number: UPN; Tolerance: 10; alternate symbols: (C1206); part number: CAP_SM-1UF,50V,10,E021800,C1206; tolerance: 10
C115 = CAP: User Part Number: UPN; Tolerance: 5; alternate symbols: (C0603); part number: CAP_SM-10PF,50V,5,E010138,C0603; tolerance: 5
C117 = CAP: User Part Number: UPN; Tolerance: 10; alternate symbols: (C0603); part number: CAP_SM-0.1UF,25V,10,E007204,C0603; tolerance: 10
C133 C135 C136 C140 = CAP: User Part Number: UPN; Tolerance: 5; alternate symbols: (C0402); part number: CAP_SM-1000PF,50V,5,E012419,C0402; tolerance: 5
C142-C144 C147 = CAP: Tolerance: 10; User Part Number: UPN; alternate symbols: (C0805H53); part number: CAP_SM-10UF,16V,10,E006166,C0805H53; tolerance: 10
C148 C150 = CAP: User Part Number: UPN; Tolerance: 5; alternate symbols: (C0402); part number: CAP_SM-560PF,50V,5,E016755,C0402; tolerance: 5
C153 C168 = CAP: User Part Number: UPN; Tolerance: 5; alternate symbols: (C0402); part number: CAP_SM-47PF,16V,5,E055986,C0402; tolerance: 5
C155 C164 = CAP: User Part Number: UPN; Tolerance: 5; alternate symbols: (C0402); part number: CAP_SM-68PF,50V,5,E042660,C0402; tolerance: 5
C157 C158 = CAP: User Part Number: UPN; Tolerance: 5; alternate symbols: (C0402); part number: CAP_SM-270PF,50V,5,E016782,C0402; tolerance: 5
C161 C165 = CAP: User Part Number: UPN; Tolerance: 5; alternate symbols: (C0402); part number: CAP_SM-150PF,50V,5,E054573,C0402; tolerance: 5
C166 C167 = CAP: User Part Number: UPN; Tolerance: 20; alternate symbols: (C0402); part number: CAP_SM-10UF,10V,20,E020928,C0402; tolerance: 20
C169-C171 = CAP: User Part Number: UPN; Tolerance: 10; alternate symbols: (C0402); part number: CAP_SM-0.1UF,25V,10,E025708,C0402; tolerance: 10
D1 D2 D6 D7 = DIOSCHOTTKY: Tolerance: N/A; User Part Number: UPN; alternate symbols: (SOD123F); part number: DIOSCHOTTKY_SM-PMEG6010CEH,115,60V,N/A,E052090,SOD123F; tolerance: N/A
D3 D4 D10 = DIOZNR: User Part Number: UPN; Tolerance: N/A; alternate symbols: (SOD123FL); part number: DIOZNR_SM-TPSMF4L30A,30V,N/A,E047953,SOD123FL; tolerance: N/A
D5 = DIOSCHOTTKY: User Part Number: UPN; Tolerance: N/A; alternate symbols: (SMA); part number: DIOSCHOTTKY_SM-NRVTSA3100ET3G,100V,N/A,E044405,SMA; tolerance: N/A
D8 D9 = DIOSCHOTTKY_6P_V5: User Part Number: UPN; Tolerance: N/A; alternate symbols: (SOT363H43); part number: DIOSCHOTTKY_6P_V5_SM-BAT54XY,115,30V,N/A,E055985,SOT363H43; tolerance: N/A
DS1 DS11 = DIOLED: Tolerance: N/A; User Part Number: UPN; alternate symbols: (LED0805); part number: DIOLED_SM-HSMS-C170,N/A,N/A,E019221,LED0805; tolerance: N/A
DS2 DS3 DS5 = DIOLED: Tolerance: N/A; User Part Number: UPN; alternate symbols: (LEDCMD28-21B); part number: DIOLED_SM-CMD28-21VGC/TR8,2.1V,N/A,E001181,LEDCMD28-21B; tolerance: N/A
DS4 = DIOLED: Tolerance: N/A; User Part Number: UPN; alternate symbols: (LED0805); part number: DIOLED_SM-HSMA-C170-T0000,N/A,N/A,E051563,LED0805; tolerance: N/A
DS6 = DIOLED_6P: Tolerance: N/A; User Part Number: UPN; alternate symbols: (LEDSMSQ134H114); part number: DIOLED_6P_SM-CLX6F-FKC-CNP1ST1E1BB7D3D3,2.1V/2.7V/3V,N/A,E039396,LEDSMSQ134H114; tolerance: N/A
DS7 DS8 = DIOLED: Tolerance: N/A; User Part Number: UPN; alternate symbols: (LXT0805); part number: DIOLED_SM-SML-LXT0805GW-TR,N/A,N/A,E005318,LXT0805; tolerance: N/A
DS9 DS10 = DIOLED: Tolerance: N/A; User Part Number: UPN; alternate symbols: (LED0603); part number: DIOLED_SM-APT1608LVBC/D,2.65V,N/A,E039384,LED0603; tolerance: N/A
E1 E3 E9 E11 E12 E16 = FERRITE: Tolerance: 25; User Part Number: UPN; alternate symbols: (L0603-2); part number: FERRITE_SM-600OHM AT 100MEGHZ,25,E038446,L0603-2; tolerance: 25
E2 = FERRITE: User Part Number: UPN; Tolerance: 25; alternate symbols: (L0603); part number: FERRITE_SM-600 OHM AT 100 MEGHZ,25,E055554,L0603; tolerance: 25
E6 = FERRITE: User Part Number: UPN; Tolerance: 25; alternate symbols: (L0603); part number: FERRITE_SM-600OHM AT 100MEGHZ,25,E047053,L0603; tolerance: 25
E18 = FERRITE: User Part Number: UPN; Tolerance: 25; alternate symbols: (L0603); part number: FERRITE_SM-470OHM AT 100MEGHZ,25,E044359,L0603; tolerance: 25
FL1 FL2 = FLTR4P_V7: User Part Number: UPN; Tolerance: N/A; alternate symbols: (FLSML154W98H98); part number: FLTR4P_V7_SM-ACT1210L-101-2P-TL00,E033324,FLSML154W98H98; tolerance: N/A
JP1 = CN4P: User Part Number: UPN; Tolerance: N/A; alternate symbols: (CNTHMHDR1X4L400W98H343); part number: CN4P_TH-TSW-104-07-G-S,E042651,CNTHMHDR1X4L400W98H343; tolerance: N/A
JP2 JP3 JP47 = CN2P: User Part Number: UPN; Tolerance: N/A; alternate symbols: (CNTHMHDR1X2L200W98H343); part number: CN2P_TH-TSW-102-07-G-S,E031850,CNTHMHDR1X2L200W98H343; tolerance: N/A
JP4 JP6 JP9 JP38 = CN3P: User Part Number: UPN; Tolerance: N/A; alternate symbols: (CNTHMHDR1X3L300W98H343); part number: CN3P_TH-TSW-103-07-G-S,E042653,CNTHMHDR1X3L300W98H343; tolerance: N/A
JP42 = CN2P: User Part Number: UPN; Tolerance: N/A; alternate symbols: (CNTHMHDR1X2L200W98H343); part number: CN2P_TH-HTSW-102-07-T-S,E027227,CNTHMHDR1X2L200W98H343; tolerance: N/A
L1-L3 L6 L8 L9 = IND: User Part Number: UPN; Tolerance: 20; alternate symbols: (L0805H57); part number: IND_SM-3.3UH,20,E033480,L0805H57; tolerance: 20
L4 L5 L10 L11 = IND: Tolerance: 5; User Part Number: UPN; alternate symbols: (L0402-3); part number: IND_SM-180NH,5,E034614,L0402-3; tolerance: 5
L7 = IND: User Part Number: UPN; Tolerance: 20; alternate symbols: (LSML213W201H59); part number: IND_SM-4.7UH,20,E039845,LSML213W201H59; tolerance: 20
L12 = IND: Tolerance: 30; User Part Number: UPN; alternate symbols: (LSMSQ189H118_A); part number: IND_SM-100UH,30,E024161,LSMSQ189H118_A; tolerance: 30
L13 = IND: User Part Number: UPN; Tolerance: 20; alternate symbols: (LSMSQ157H122); part number: IND_SM-4.7UH,20,E013623,LSMSQ157H122; tolerance: 20
P1 = CN3P: Tolerance: N/A; User Part Number: UPN; alternate symbols: (CNCUI-PJ-102A); part number: CN3P_TH-PJ-102AH,E010074,CNCUI-PJ-102A_SLOTPAD; tolerance: N/A
P2 = CN2P: Tolerance: N/A; User Part Number: UPN; alternate symbols: (CNWEIDMULLER171602); part number: CN2P_TH-1716020000,E017764,CNWEIDMULLER171602; tolerance: N/A
P3 P5 = CN4P_V4: User Part Number: UPN; Tolerance: N/A; alternate symbols: (CNCUIRCJ-01); part number: CN4P_V4_TH-RCJ-011,E020612,CNCUIRCJ-01; tolerance: N/A
P4 = CN3P_V16: Tolerance: N/A; User Part Number: UPN; alternate symbols: (CNCLIFF_FCR684208R); part number: CN3P_V16_TH-FCR684208R,E034605,CNCLIFF_FCR684208R; tolerance: N/A
P6 = CN3P_V17: Tolerance: N/A; User Part Number: UPN; alternate symbols: (CNCLIFF_FCR684208T); part number: CN3P_V17_TH-FCR684208T,E034606,CNCLIFF_FCR684208T; tolerance: N/A
P8 = CN10P: User Part Number: UPN; Tolerance: N/A; alternate symbols: (CNSAMTEC2X5H338LD36); part number: CN10P_TH-TSW-105-07-G-D,E026229,CNSAMTEC2X5H338LD36; tolerance: N/A
P10 P22 = MOD_RJE73_188_00XXX: User Part Number: UPN; Tolerance: N/A; alternate symbols: (MRJE73-188-00XXX); part number: MOD_RJE73_188_00XXX_TH-RJE73-188-00210,E056744,MRJE73-188-00XXX; tolerance: N/A
P15 = CN32P_ODD_EVEN: Tolerance: N/A; User Part Number: UPN; alternate symbols: (CNBERG2X16H330LD36); part number: CN32P_ODD_EVEN_TH-TSW-116-08-G-D,E000802,CNBERG2X16H330LD36; tolerance: N/A
P23 TP1-TP26 = NCTESTPAD: Tolerance: N/A; User Part Number: UPN; alternate symbols: (TPC65D45); part number: NCTESTPAD_TH-TESTPAD,E013404,TPC65D45; tolerance: N/A
P28 P29 = CN5P_V3: User Part Number: UPN; Tolerance: N/A; alternate symbols: (CNCUISJ1-3525NG); part number: CN5P_V3_TH-SJ1-3525NG,E019255,CNCUISJ1-3525NG; tolerance: N/A
P30 = CN10P: Tolerance: N/A; User Part Number: UPN; alternate symbols: (CN3MN2510-6002RB); part number: CN10P_TH-N2510-6002-RB,E005954,CN3MN2510-6002RB; tolerance: N/A
P32 = CN100P_V2: Tolerance: N/A; User Part Number: UPN; alternate symbols: (CNSAMTECLSS-150-01-X-DV-A); part number: CN100P_V2_SM-LSS-150-01-L-DV-A-K,E035696,CNSAMTECLSS-150-01-X-DV-A; tolerance: N/A
Q1 = TRANNMOSFET_DUAL: Tolerance: N/A; User Part Number: UPN; alternate symbols: (SO8NB-5); part number: TRANNMOSFET_DUAL_SM-DMNH6022SSDQ-13,E054897,SO8NB-5; tolerance: N/A
Q2 = TRANOPTO4P_V2: Tolerance: N/A; User Part Number: UPN; alternate symbols: (SO4H96); part number: TRANOPTO4P_V2_SM-TLX9291A(GBTPL,F,E049883,SO4H96; tolerance: N/A
Q3 = TRANTIP32B: User Part Number: UPN; Tolerance: N/A; alternate symbols: (TO252); part number: TRANTIP32B_SM-STD2805T4,E013981,TO252; tolerance: N/A
Q4 = TRANNMOSFET_V15: User Part Number: UPN; Tolerance: N/A; alternate symbols: (POWERDI5060-8); part number: TRANNMOSFET_V15_SM-DMTH8012LPSQ-13,E045036,POWERDI5060-8; tolerance: N/A
R1 R65 R136 R220 = RES: User Part Number: UPN; Tolerance: 5; alternate symbols: (R0402); part number: RES_SM-100,E003443,1/10W,5,R0402; tolerance: 5
R2 R5 R7 R9 R12 R21 R42 R80 R82 R83 R95 R101 R107 R110 R115 R119 R135 R154 R178-R180 R184 R187 R231 R238 = RES: User Part Number: UPN; Tolerance: 1; alternate symbols: (R0402); part number: RES_SM-10K,E003751,1/10W,1,R0402; tolerance: 1
R3 R6 R8 R28 R37 R43 R54 R55 R57 R60-R63 R70 R77 R79 R85-R87 R89 R91 R92 R94 R97 R100 R106 R111 R113 R124 R125 R127 R134 R157 R163 R165 R166 R169 R171-R174 R177 R181 R189 R210 R223 R225-R228 R233 R234 = RES: User Part Number: UPN; Tolerance: JUMPER; alternate symbols: (R0402); part number: RES_SM-0,E003438,1/10W,JUMPER,R0402; tolerance: JUMPER
R4 R33 R36 R155 R175 R176 = RES: User Part Number: UPN; Tolerance: 1; alternate symbols: (R0402); part number: RES_SM-1K,E003763,1/10W,1,R0402; tolerance: 1
R10 R32 = RES: User Part Number: UPN; Tolerance: 1; alternate symbols: (R0603); part number: RES_SM-4.7K,E028693,1/4W,1,R0603; tolerance: 1
R11 R14 R25 R29 R35 R44 R45 R47-R52 R58 R59 R64 R66-R69 R71 R76 R81 R84 R88 R90 R98 R102-R105 R108 R109 R114 R116 R120 R121 R130-R132 R138 R140 R141 R158 R183 R193 R195 R199 R203 R232 R235 R240-R242 = RES: User Part Number: UPN; Tolerance: 5; alternate symbols: (R0402); part number: RES_SM-33,E003452,1/10W,5,R0402; tolerance: 5
R13 = RES: User Part Number: UPN; Tolerance: 1; alternate symbols: (R0603); part number: RES_SM-22K,E019090,1/10W,1,R0603; tolerance: 1
R15 R16 R19 R22 R24 R26 R30 R74 R133 R137 R139 R142 R143 R146-R148 R185 R190 R243 = RES: User Part Number: UPN; Tolerance: 1; alternate symbols: (R0402); part number: RES_SM-10K,E031669,1/16W,1,R0402; tolerance: 1
R17 = RES: User Part Number: UPN; Tolerance: 1; alternate symbols: (R0402); part number: RES_SM-4.42MEG,E054896,1/16W,1,R0402; tolerance: 1
R18 = RES: Tolerance: 1; User Part Number: UPN; alternate symbols: (R1206-2); part number: RES_SM-0.012,E026386,1/2W,1,R1206-2; tolerance: 1
R20 = RES: User Part Number: UPN; Tolerance: 1; alternate symbols: (R0402); part number: RES_SM-88.7K,E020516,1/10W,1,R0402; tolerance: 1
R23 = RES: User Part Number: UPN; Tolerance: 0.1; alternate symbols: (R0402); part number: RES_SM-11.3K,E019952,1/16W,0.1,R0402; tolerance: 0.1
R27 = RES: User Part Number: UPN; Tolerance: 1; alternate symbols: (R0402); part number: RES_SM-1MEG,E041482,1/16W,1,R0402; tolerance: 1
R31 R96 R112 = RES: User Part Number: UPN; Tolerance: 5; alternate symbols: (R1206); part number: RES_SM-0,E010093,1/4W,5,R1206; tolerance: 5
R34 R38 = RES: User Part Number: UPN; Tolerance: 1; alternate symbols: (R0402); part number: RES_SM-475,E008186,1/10W,1,R0402; tolerance: 1
R39 R53 R122 R126 = RES: User Part Number: UPN; Tolerance: 1; alternate symbols: (R0402); part number: RES_SM-2.55K,E014065,1/16W,1,R0402; tolerance: 1
R40 R41 = RES: Tolerance: 5; User Part Number: UPN; alternate symbols: (R1210); part number: RES_SM-100,E013617,1/2W,5,R1210; tolerance: 5
R46 = RES: User Part Number: UPN; Tolerance: 1; alternate symbols: (R0402); part number: RES_SM-205,E010569,1/10W,1,R0402; tolerance: 1
R56 R78 = RES: Tolerance: 1; User Part Number: UPN; alternate symbols: (R1210); part number: RES_SM-120,E033377,3/4W,1,R1210; tolerance: 1
R72 R73 R93 R128 R144 R145 R149 R150 R156 R159 R161 R170 R244 R246 R250 = RES: User Part Number: UPN; Tolerance: 1; alternate symbols: (R0402); part number: RES_SM-100K,E003796,1/10W,1,R0402; tolerance: 1
R75 = RES: User Part Number: UPN; Tolerance: 1; alternate symbols: (R0402); part number: RES_SM-3.32K,E034634,1/10W,1,R0402; tolerance: 1
R99 = RES: User Part Number: UPN; Tolerance: 1; alternate symbols: (R0402); part number: RES_SM-4.32K,E003776,1/10W,1,R0402; tolerance: 1
R117 = RES: User Part Number: UPN; Tolerance: 1; alternate symbols: (R1206); part number: RES_SM-562,E003240,1/4W,1,R1206; tolerance: 1
R118 = RES: User Part Number: UPN; Tolerance: 0.1; alternate symbols: (R0402); part number: RES_SM-10K,E012474,1/16W,0.1,R0402; tolerance: 0.1
R123 R129 R201 R202 R204 R205 R207 R208 R213 R214 = RES: User Part Number: UPN; Tolerance: 1; alternate symbols: (R0402); part number: RES_SM-5.36K,E015300,1/10W,1,R0402; tolerance: 1
R151-R153 = RES: User Part Number: UPN; Tolerance: 1; alternate symbols: (R0805); part number: RES_SM-10,E003557,1/8W,1,R0805; tolerance: 1
R160 = RES: User Part Number: UPN; Tolerance: 1; alternate symbols: (R0402); part number: RES_SM-31.6K,E019881,1/10W,1,R0402; tolerance: 1
R162 = RES: User Part Number: UPN; Tolerance: 0.5; alternate symbols: (R0603); part number: RES_SM-24.9K,E011717,1/16W,0.5,R0603; tolerance: 0.5
R164 = RES: User Part Number: UPN; Tolerance: 1; alternate symbols: (R0402); part number: RES_SM-10.2K,E019451,1/16W,1,R0402; tolerance: 1
R167 = RES: User Part Number: UPN; Tolerance: 1; alternate symbols: (R0402); part number: RES_SM-53.6K,E023305,1/16W,1,R0402; tolerance: 1
R168 = RES: User Part Number: UPN; Tolerance: 0.5; alternate symbols: (R0805); part number: RES_SM-12,E003974,1/10W,0.5,R0805; tolerance: 0.5
R182 = RES: Tolerance: 1; User Part Number: UPN; alternate symbols: (R1206-2); part number: RES_SM-0.05,E032040,1W,1,R1206-2; tolerance: 1
R186 = RES: User Part Number: UPN; Tolerance: 1; alternate symbols: (R0402); part number: RES_SM-0.5,E023524,1/16W,1,R0402; tolerance: 1
R188 = RES: User Part Number: UPN; Tolerance: 1; alternate symbols: (R0603); part number: RES_SM-75,E003702,1/10W,1,R0603; tolerance: 1
R192 R211 R215 R216 = RES: User Part Number: UPN; Tolerance: 1; alternate symbols: (R0402); part number: RES_SM-5.62K,E034039,1/10W,1,R0402; tolerance: 1
R194 R212 R217 R218 = RES: User Part Number: UPN; Tolerance: 1; alternate symbols: (R0402); part number: RES_SM-11K,E025320,1/16W,1,R0402; tolerance: 1
R196-R198 R200 = RES: User Part Number: UPN; Tolerance: 1; alternate symbols: (R0603); part number: RES_SM-237,E010703,1/10W,1,R0603; tolerance: 1
R206 = RES: User Part Number: UPN; Tolerance: 1; alternate symbols: (R0402); part number: RES_SM-249,E003759,1/16W,1,R0402; tolerance: 1
R209 = RES: User Part Number: UPN; Tolerance: 1; alternate symbols: (R0402); part number: RES_SM-110,E055088,1/10W,1,R0402; tolerance: 1
R219 R222 = RES: User Part Number: UPN; Tolerance: 1; alternate symbols: (R0402); part number: RES_SM-3.01K,E027299,1/10W,1,R0402; tolerance: 1
R221 R224 = RES: User Part Number: UPN; Tolerance: 1; alternate symbols: (R0402); part number: RES_SM-1.5K,E003782,1/10W,1,R0402; tolerance: 1
R236 R237 = RES: User Part Number: UPN; Tolerance: 1; alternate symbols: (R0402); part number: RES_SM-100,E016329,1/10W,1,R0402; tolerance: 1
R239 = RES: User Part Number: UPN; Tolerance: 5; alternate symbols: (R0402); part number: RES_SM-330,E003462,1/10W,5,R0402; tolerance: 5
R247 R249 = RES: User Part Number: UPN; Tolerance: 1; alternate symbols: (R1206); part number: RES_SM-2.74K,E003202,1/4W,1,R1206; tolerance: 1
R248 = RES: User Part Number: UPN; Tolerance: 1; alternate symbols: (R0402); part number: RES_SM-365,E028356,1/10W,1,R0402; tolerance: 1
S1 = SWDPDT_V5: Tolerance: N/A; User Part Number: UPN; alternate symbols: (SWSML354W142H217); part number: SWDPDT_V5_SM-JS202011SCQN,E026595,SWSML354W142H217; tolerance: N/A
SW1 = SWSPST4PIN_GND: Tolerance: N/A; User Part Number: UPN; alternate symbols: (SWSML165W110H75-G); part number: SWSPST4PIN_GND_SM-KMR223GLFG,E040082,SWSML165W110H75-G; tolerance: N/A
T1 = XFMR7P_V2: User Part Number: UPN; Tolerance: N/A; alternate symbols: (TSML185W127H114_B); part number: XFMR7P_V2_SM-74930000,E042298,TSML185W127H114_A; tolerance: N/A
T2 T3 = XFMR8P_V26: User Part Number: UPN; Tolerance: N/A; alternate symbols: (TSML387W323H220); part number: XFMR8P_V26_SM-SC947-02LF,E055929,TSML387W323H220; tolerance: N/A
U1 U24 U25 = 7408_V3: User Part Number: UPN; Tolerance: N/A; alternate symbols: (SOT23-5L-2); part number: 7408_V3_SM-SN74LVC1G08QDBVRQ1,E040048,SOT23-5L-2; tolerance: N/A
U2 = ADM6315: User Part Number: UPN; Tolerance: N/A; alternate symbols: (SOT143A); part number: ADM6315_SM-ADM6315-31D1ARTZ,E019835,SOT143A; tolerance: N/A
U3 = ADLTC4368_V2: Tolerance: N/A; User Part Number: UPN; alternate symbols: (DFN10_3X3_PAD2_38X1_65_05-08-1699); part number: ADLTC4368_V2_SM-LTC4368IDD-2#PBF,E058859,DFN10_3X3_PAD2_38X1_65_05-08-1699; tolerance: N/A
U4 U26 U27 = 741G125: Tolerance: N/A; User Part Number: UPN; alternate symbols: (SC70-5); part number: 741G125_SM-SN74CBTLV1G125DCKR,E020171,SC70-5; tolerance: N/A
U5 U17 U18 = ADA4841_2: Tolerance: N/A; User Part Number: UPN; alternate symbols: (SO8); part number: ADA4841_2_SM-ADA4841-2YRZ,E018522,SO8; tolerance: N/A
U6 = ADAU145X: User Part Number: UPN; Tolerance: N/A; alternate symbols: (QFN72_10X10_PAD5_3X5_3); part number: ADAU145X_SM-ADAU1452WBCPZ,E017625,QFN72_10X10_PAD5_3X5_3; tolerance: N/A
U7 = AD1937: Tolerance: N/A; User Part Number: UPN; alternate symbols: (LQFP64); part number: AD1937_SM-AD1937WBSTZ,E056121,LQFP64; tolerance: N/A
U8 = ADG774: Tolerance: N/A; User Part Number: UPN; alternate symbols: (SO16NB-2); part number: ADG774_SM-ADG774BRZ,E046658,SO16NB-2; tolerance: N/A
U9 = AD243XW: Tolerance: N/A; User Part Number: UPN; alternate symbols: (SKTIRONWOOD_SBT-QFN-4022_QFN48_7X7_PAD4_1X4_1_NPM); part number: AD243XW_SM-AD2437,E049687,QFN48_7X7_PAD4_1X4_1; tolerance: N/A
